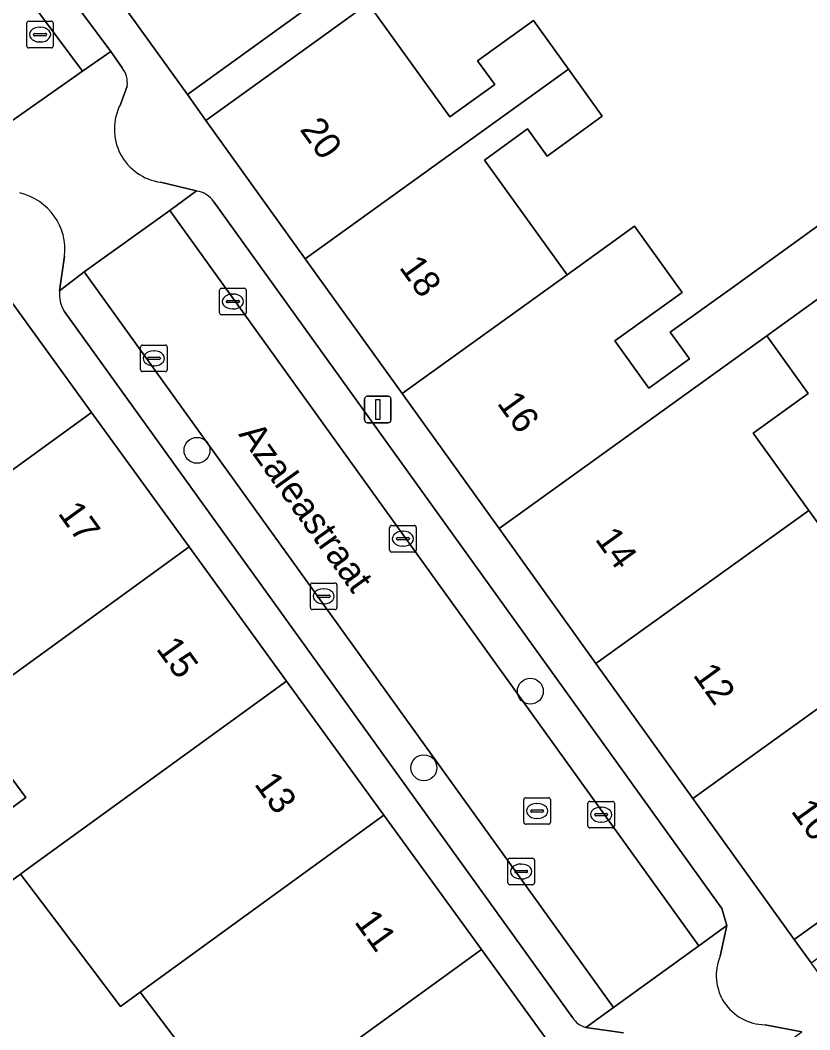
# Model space of a CAD drawing. Extents: x 161881 to 162523, y 381678 to 382381.
# Drawn here: x 162168.42 to 162198.15, y 381942.76 to 381980.78 of the extents above; entities that cross this region are included whole.
import ezdxf

# ---------------------------------------------------------------- set-up
doc = ezdxf.new("R2010")
doc.units = 0
for name, color, linetype in [('IMGEO_Boom', 7, 'Continuous'), ('IMGEO_Erf', 7, 'Continuous'), ('IMGEO_Kolk', 7, 'Continuous'), ('IMGEO_Lichtmast', 7, 'Continuous'), ('IMGEO_Openbare_ruimte_label', 7, 'Continuous'), ('IMGEO_Pand', 7, 'Continuous'), ('IMGEO_Pand_nummerreeks', 7, 'Continuous'), ('IMGEO_Parkeervlak_open', 7, 'Continuous'), ('IMGEO_Rijbaan_lokaal_open', 7, 'Continuous'), ('IMGEO_Rioolput', 7, 'Continuous'), ('IMGEO_Voetpad_open', 7, 'Continuous')]:
    doc.layers.add(name, color=color, linetype=linetype)

msp = doc.modelspace()

# ---------------------------------------------------------------- linework, layer by layer
at = {"layer": 'IMGEO_Boom'}
for centre in [(162175.078, 381964.578), (162187.627, 381955.507), (162183.621, 381952.624)]:
    msp.add_circle(centre, 0.489, dxfattribs=at)
at = {"layer": 'IMGEO_Erf'}
for points in [[(162181.521, 381981.402), (162184.595, 381977.135), (162186.287, 381978.354), (162185.642, 381979.251), (162187.741, 381980.763), (162189.059, 381978.933), (162190.337, 381977.159), (162188.256, 381975.66), (162187.522, 381976.679), (162185.899, 381975.51), (162189.013, 381971.188), (162191.552, 381973.017), (162193.346, 381970.527), (162190.807, 381968.698), (162192.09, 381966.917), (162193.621, 381968.02), (162192.896, 381969.027), (162195.221, 381970.702), (162200.713, 381974.659)], [(162204.344, 381974.538), (162196.525, 381968.892), (162198.089, 381966.721), (162196.011, 381965.224), (162198.108, 381962.315), (162199.336, 381960.612)], [(162175.389, 381940.937), (162172.942, 381944.178), (162172.196, 381943.637), (162169.811, 381946.798), (162168.435, 381948.622), (162167.308, 381947.805), (162167.043, 381947.612), (162165.741, 381949.371), (162167.366, 381950.575), (162168.628, 381951.51), (162166.234, 381954.743), (162164.203, 381953.269), (162164.056, 381953.468), (162163.85, 381953.747), (162161.313, 381957.173), (162162.248, 381957.851), (162161.421, 381958.968), (162160.092, 381960.763), (162162.184, 381962.312), (162162.831, 381961.439), (162164.467, 381962.65), (162161.41, 381966.864), (162140.416, 381951.63)]]:
    msp.add_lwpolyline(points, dxfattribs=at)
at = {"layer": 'IMGEO_Kolk'}
for p, q in [((162168.667, 381979.809), (162168.667, 381980.661)), ((162168.742, 381980.735), (162169.594, 381980.735)), ((162169.155, 381980.515), (162169.18, 381980.515)), ((162169.668, 381980.661), (162169.668, 381979.809)), ((162168.926, 381980.229), (162168.926, 381980.241)), ((162169.364, 381980.192), (162168.966, 381980.192)), ((162168.969, 381980.278), (162169.367, 381980.278)), ((162169.41, 381980.241), (162169.41, 381980.229)), ((162169.594, 381979.735), (162168.742, 381979.735)), ((162169.178, 381979.955), (162169.153, 381979.955)), ((162175.93, 381969.757), (162175.93, 381970.609)), ((162176.005, 381970.683), (162176.857, 381970.683)), ((162176.931, 381970.609), (162176.931, 381969.757)), ((162176.232, 381970.226), (162176.63, 381970.226)), ((162176.418, 381970.463), (162176.443, 381970.463)), ((162176.189, 381970.177), (162176.189, 381970.189)), ((162176.627, 381970.14), (162176.229, 381970.14)), ((162176.441, 381969.903), (162176.416, 381969.903)), ((162176.673, 381970.189), (162176.673, 381970.177)), ((162176.857, 381969.683), (162176.005, 381969.683)), ((162172.955, 381967.616), (162172.955, 381968.468)), ((162173.03, 381968.542), (162173.882, 381968.542)), ((162173.443, 381968.322), (162173.468, 381968.322)), ((162173.956, 381968.468), (162173.956, 381967.616)), ((162173.214, 381968.036), (162173.214, 381968.048)), ((162173.652, 381967.999), (162173.254, 381967.999)), ((162173.257, 381968.085), (162173.655, 381968.085)), ((162173.698, 381968.048), (162173.698, 381968.036)), ((162173.466, 381967.762), (162173.441, 381967.762)), ((162173.882, 381967.542), (162173.03, 381967.542)), ((162182.331, 381960.823), (162182.331, 381961.675)), ((162182.406, 381961.749), (162183.258, 381961.749)), ((162182.819, 381961.529), (162182.844, 381961.529)), ((162183.332, 381961.675), (162183.332, 381960.823)), ((162182.59, 381961.243), (162182.59, 381961.255)), ((162183.028, 381961.206), (162182.63, 381961.206)), ((162182.633, 381961.292), (162183.031, 381961.292)), ((162183.074, 381961.255), (162183.074, 381961.243)), ((162183.258, 381960.749), (162182.406, 381960.749)), ((162182.842, 381960.969), (162182.817, 381960.969)), ((162179.421, 381959.581), (162180.273, 381959.581)), ((162179.346, 381958.655), (162179.346, 381959.507)), ((162179.834, 381959.361), (162179.859, 381959.361)), ((162180.347, 381959.507), (162180.347, 381958.655)), ((162179.605, 381959.075), (162179.605, 381959.087)), ((162180.043, 381959.038), (162179.645, 381959.038)), ((162179.648, 381959.124), (162180.046, 381959.124)), ((162180.089, 381959.087), (162180.089, 381959.075)), ((162180.273, 381958.581), (162179.421, 381958.581)), ((162179.857, 381958.801), (162179.832, 381958.801)), ((162189.792, 381950.433), (162189.792, 381951.285)), ((162189.867, 381951.359), (162190.719, 381951.359)), ((162190.793, 381951.285), (162190.793, 381950.433)), ((162190.051, 381950.853), (162190.051, 381950.865)), ((162190.094, 381950.902), (162190.492, 381950.902)), ((162190.28, 381951.139), (162190.305, 381951.139)), ((162190.535, 381950.865), (162190.535, 381950.853)), ((162190.489, 381950.816), (162190.091, 381950.816)), ((162190.303, 381950.579), (162190.278, 381950.579)), ((162190.719, 381950.359), (162189.867, 381950.359)), ((162186.783, 381948.291), (162186.783, 381949.143)), ((162186.858, 381949.217), (162187.71, 381949.217)), ((162187.271, 381948.997), (162187.296, 381948.997)), ((162187.784, 381949.143), (162187.784, 381948.291)), ((162187.042, 381948.711), (162187.042, 381948.723)), ((162187.48, 381948.674), (162187.082, 381948.674)), ((162187.085, 381948.76), (162187.483, 381948.76)), ((162187.526, 381948.723), (162187.526, 381948.711)), ((162187.71, 381948.217), (162186.858, 381948.217)), ((162187.294, 381948.437), (162187.269, 381948.437))]:
    msp.add_line(p, q, dxfattribs=at)
for points in [[(162168.667, 381979.809), (162168.667, 381980.661)], [(162168.742, 381980.735), (162169.594, 381980.735)], [(162169.668, 381980.661), (162169.668, 381979.809)], [(162169.594, 381979.735), (162168.742, 381979.735)], [(162175.93, 381969.757), (162175.93, 381970.609)], [(162176.005, 381970.683), (162176.857, 381970.683)], [(162176.931, 381970.609), (162176.931, 381969.757)], [(162176.857, 381969.683), (162176.005, 381969.683)], [(162172.955, 381967.616), (162172.955, 381968.468)], [(162173.03, 381968.542), (162173.882, 381968.542)], [(162173.956, 381968.468), (162173.956, 381967.616)], [(162173.882, 381967.542), (162173.03, 381967.542)], [(162182.331, 381960.823), (162182.331, 381961.675)], [(162182.406, 381961.749), (162183.258, 381961.749)], [(162183.332, 381961.675), (162183.332, 381960.823)], [(162183.258, 381960.749), (162182.406, 381960.749)], [(162179.421, 381959.581), (162180.273, 381959.581)], [(162179.346, 381958.655), (162179.346, 381959.507)], [(162180.347, 381959.507), (162180.347, 381958.655)], [(162180.273, 381958.581), (162179.421, 381958.581)], [(162189.792, 381950.433), (162189.792, 381951.285)], [(162189.867, 381951.359), (162190.719, 381951.359)], [(162190.793, 381951.285), (162190.793, 381950.433)], [(162190.719, 381950.359), (162189.867, 381950.359)], [(162186.783, 381948.291), (162186.783, 381949.143)], [(162186.858, 381949.217), (162187.71, 381949.217)], [(162187.784, 381949.143), (162187.784, 381948.291)], [(162187.71, 381948.217), (162186.858, 381948.217)]]:
    msp.add_lwpolyline(points, dxfattribs=at)
for centre, radius, start, end in [((162168.744, 381980.659), 0.0765, 91.552, 178.448), ((162168.744, 381980.659), 0.0765, 91.552, 178.448), ((162169.592, 381980.659), 0.0765, 1.552, 88.448), ((162169.592, 381980.659), 0.0765, 1.552, 88.448), ((162168.966, 381980.238), 0.0403, 85.8775, 175.7526), ((162168.963, 381980.228), 0.0366, 178.938, 274.7102), ((162169.367, 381980.235), 0.043, 264.8664, 352.4533), ((162169.371, 381980.24), 0.0386, 1.7309, 96.639), ((162168.744, 381979.811), 0.0765, 181.552, 268.448), ((162168.744, 381979.811), 0.0765, 181.552, 268.448), ((162169.592, 381979.811), 0.0765, 271.552, 358.448), ((162169.592, 381979.811), 0.0765, 271.552, 358.448), ((162176.007, 381970.607), 0.0765, 91.552, 178.448), ((162176.007, 381970.607), 0.0765, 91.552, 178.448), ((162176.855, 381970.607), 0.0765, 1.552, 88.448), ((162176.855, 381970.607), 0.0765, 1.552, 88.448), ((162176.229, 381970.186), 0.0403, 85.8775, 175.7526), ((162176.634, 381970.188), 0.0386, 1.7309, 96.639), ((162176.226, 381970.176), 0.0366, 178.938, 274.7102), ((162176.63, 381970.183), 0.043, 264.8664, 352.4533), ((162176.007, 381969.759), 0.0765, 181.552, 268.448), ((162176.007, 381969.759), 0.0765, 181.552, 268.448), ((162176.855, 381969.759), 0.0765, 271.552, 358.448), ((162176.855, 381969.759), 0.0765, 271.552, 358.448), ((162173.032, 381968.466), 0.0765, 91.552, 178.448), ((162173.032, 381968.466), 0.0765, 91.552, 178.448), ((162173.88, 381968.466), 0.0765, 1.552, 88.448), ((162173.88, 381968.466), 0.0765, 1.552, 88.448), ((162173.254, 381968.045), 0.0403, 85.8775, 175.7526), ((162173.251, 381968.035), 0.0366, 178.938, 274.7102), ((162173.655, 381968.042), 0.043, 264.8664, 352.4533), ((162173.659, 381968.047), 0.0386, 1.7309, 96.639), ((162173.032, 381967.618), 0.0765, 181.552, 268.448), ((162173.032, 381967.618), 0.0765, 181.552, 268.448), ((162173.88, 381967.618), 0.0765, 271.552, 358.448), ((162173.88, 381967.618), 0.0765, 271.552, 358.448), ((162182.408, 381961.673), 0.0765, 91.552, 178.448), ((162182.408, 381961.673), 0.0765, 91.552, 178.448), ((162183.256, 381961.673), 0.0765, 1.552, 88.448), ((162183.256, 381961.673), 0.0765, 1.552, 88.448), ((162182.63, 381961.252), 0.0403, 85.8775, 175.7526), ((162182.627, 381961.242), 0.0366, 178.938, 274.7102), ((162183.031, 381961.249), 0.043, 264.8664, 352.4533), ((162183.035, 381961.254), 0.0386, 1.7309, 96.639), ((162182.408, 381960.825), 0.0765, 181.552, 268.448), ((162182.408, 381960.825), 0.0765, 181.552, 268.448), ((162183.256, 381960.825), 0.0765, 271.552, 358.448), ((162183.256, 381960.825), 0.0765, 271.552, 358.448), ((162179.423, 381959.505), 0.0765, 91.552, 178.448), ((162179.423, 381959.505), 0.0765, 91.552, 178.448), ((162180.271, 381959.505), 0.0765, 1.552, 88.448), ((162180.271, 381959.505), 0.0765, 1.552, 88.448), ((162179.645, 381959.084), 0.0403, 85.8775, 175.7526), ((162179.642, 381959.074), 0.0366, 178.938, 274.7102), ((162180.046, 381959.081), 0.043, 264.8664, 352.4533), ((162180.05, 381959.086), 0.0386, 1.7309, 96.639), ((162179.423, 381958.657), 0.0765, 181.552, 268.448), ((162179.423, 381958.657), 0.0765, 181.552, 268.448), ((162180.271, 381958.657), 0.0765, 271.552, 358.448), ((162180.271, 381958.657), 0.0765, 271.552, 358.448), ((162189.869, 381951.283), 0.0765, 91.552, 178.448), ((162189.869, 381951.283), 0.0765, 91.552, 178.448), ((162190.717, 381951.283), 0.0765, 1.552, 88.448), ((162190.717, 381951.283), 0.0765, 1.552, 88.448), ((162190.091, 381950.862), 0.0403, 85.8775, 175.7526), ((162190.088, 381950.852), 0.0366, 178.938, 274.7102), ((162190.492, 381950.859), 0.043, 264.8664, 352.4533), ((162190.496, 381950.864), 0.0386, 1.7309, 96.639), ((162189.869, 381950.435), 0.0765, 181.552, 268.448), ((162189.869, 381950.435), 0.0765, 181.552, 268.448), ((162190.717, 381950.435), 0.0765, 271.552, 358.448), ((162190.717, 381950.435), 0.0765, 271.552, 358.448), ((162186.86, 381949.141), 0.0765, 91.552, 178.448), ((162186.86, 381949.141), 0.0765, 91.552, 178.448), ((162187.708, 381949.141), 0.0765, 1.552, 88.448), ((162187.708, 381949.141), 0.0765, 1.552, 88.448), ((162187.082, 381948.72), 0.0403, 85.8775, 175.7526), ((162187.079, 381948.71), 0.0366, 178.938, 274.7102), ((162187.483, 381948.717), 0.043, 264.8664, 352.4533), ((162187.487, 381948.722), 0.0386, 1.7309, 96.639), ((162186.86, 381948.293), 0.0765, 181.552, 268.448), ((162186.86, 381948.293), 0.0765, 181.552, 268.448), ((162187.708, 381948.293), 0.0765, 271.552, 358.448), ((162187.708, 381948.293), 0.0765, 271.552, 358.448)]:
    msp.add_arc(centre, radius, start, end, dxfattribs=at)
for centre, major_axis, ratio, start_param, end_param in [((162169.154, 381980.235), (-0.387, 0.002), 0.722429, 4.712389, 7.853982), ((162169.179, 381980.235), (-0.39, 0.002), 0.717154, 1.570796, 4.712389), ((162176.417, 381970.183), (-0.387, 0.002), 0.722429, 4.712389, 7.853982), ((162176.442, 381970.183), (-0.39, 0.002), 0.717154, 1.570796, 4.712389), ((162173.442, 381968.042), (-0.387, 0.002), 0.722429, 4.712389, 7.853982), ((162173.467, 381968.042), (-0.39, 0.002), 0.717154, 1.570796, 4.712389), ((162182.818, 381961.249), (-0.387, 0.002), 0.722429, 4.712389, 7.853982), ((162182.843, 381961.249), (-0.39, 0.002), 0.717154, 1.570796, 4.712389), ((162179.833, 381959.081), (-0.387, 0.002), 0.722429, 4.712389, 7.853982), ((162179.858, 381959.081), (-0.39, 0.002), 0.717154, 1.570796, 4.712389), ((162190.279, 381950.859), (-0.387, 0.002), 0.722429, 4.712389, 7.853982), ((162190.304, 381950.859), (-0.39, 0.002), 0.717154, 1.570796, 4.712389), ((162187.27, 381948.717), (-0.387, 0.002), 0.722429, 4.712389, 7.853982), ((162187.295, 381948.717), (-0.39, 0.002), 0.717154, 1.570796, 4.712389)]:
    msp.add_ellipse(centre, major_axis=major_axis, ratio=ratio, start_param=start_param, end_param=end_param, dxfattribs=at)
at = {"layer": 'IMGEO_Lichtmast'}
for p, q in [((162181.387, 381965.712), (162181.387, 381966.512)), ((162181.387, 381966.512), (162181.387, 381965.712)), ((162181.487, 381966.612), (162182.277, 381966.612)), ((162182.277, 381966.612), (162181.487, 381966.612)), ((162182.377, 381966.512), (162182.377, 381965.712)), ((162182.377, 381965.712), (162182.377, 381966.512)), ((162182.277, 381965.612), (162181.487, 381965.612)), ((162181.487, 381965.612), (162182.277, 381965.612))]:
    msp.add_line(p, q, dxfattribs=at)
msp.add_lwpolyline([(162181.807, 381966.487), (162181.957, 381966.487), (162181.957, 381965.737), (162181.807, 381965.737), (162181.807, 381966.487)], dxfattribs=at)
for centre, start, end in [((162181.487, 381966.512), 90, 180), ((162181.487, 381966.512), 90, 180), ((162182.277, 381966.512), 0, 90), ((162182.277, 381966.512), 360, 90), ((162181.487, 381965.712), 180, 270), ((162181.487, 381965.712), 180, 270), ((162182.277, 381965.712), 270, 0), ((162182.277, 381965.712), 270, 0)]:
    msp.add_arc(centre, 0.1, start, end, dxfattribs=at)
at = {"layer": 'IMGEO_Pand'}
for points in [[(162170.985, 381983.17), (162174.716, 381977.972), (162178.91, 381980.999), (162180.808, 381982.369), (162177.724, 381986.645), (162179.455, 381987.894), (162180.106, 381986.991), (162180.436, 381986.533), (162183.968, 381989.079), (162182.33, 381991.35)], [(162179.151, 381971.795), (162189.059, 381978.933), (162187.741, 381980.763), (162185.642, 381979.251), (162186.287, 381978.354), (162184.595, 381977.135), (162181.521, 381981.402), (162179.573, 381979.999), (162175.413, 381977.002)], [(162179.151, 381971.795), (162182.8, 381966.712), (162189.013, 381971.188), (162185.899, 381975.51), (162187.522, 381976.679), (162188.256, 381975.66), (162190.337, 381977.159), (162189.059, 381978.933)], [(162190.807, 381968.698), (162193.346, 381970.527), (162191.552, 381973.017), (162189.013, 381971.188), (162182.8, 381966.712), (162186.45, 381961.629), (162196.525, 381968.892), (162204.344, 381974.538), (162203.223, 381976.093), (162200.891, 381974.412), (162200.713, 381974.659), (162195.221, 381970.702), (162192.896, 381969.027), (162193.621, 381968.02), (162192.09, 381966.917)], [(162161.421, 381958.968), (162171.112, 381966), (162167.356, 381971.177), (162163.309, 381968.242), (162161.41, 381966.864), (162164.467, 381962.65), (162162.831, 381961.439), (162162.184, 381962.312), (162160.092, 381960.763)], [(162196.011, 381965.224), (162198.089, 381966.721), (162196.525, 381968.892), (162186.45, 381961.629), (162190.099, 381956.545), (162198.108, 381962.315)], [(162174.78, 381960.944), (162171.112, 381966), (162161.421, 381958.968), (162162.248, 381957.851), (162161.313, 381957.173), (162163.85, 381953.747), (162164.056, 381953.468), (162164.203, 381953.269), (162166.234, 381954.743)], [(162203.804, 381958.705), (162202.529, 381960.475), (162200.492, 381959.008), (162199.591, 381960.257), (162199.336, 381960.612), (162198.108, 381962.315), (162190.099, 381956.545), (162193.749, 381951.462)], [(162178.448, 381955.888), (162174.78, 381960.944), (162166.234, 381954.743), (162168.628, 381951.51), (162167.366, 381950.575), (162165.741, 381949.371), (162167.043, 381947.612), (162167.308, 381947.805), (162168.435, 381948.622), (162168.68, 381948.8)], [(162201.409, 381954.149), (162203.12, 381955.382), (162205.146, 381956.842), (162203.804, 381958.705), (162193.749, 381951.462), (162197.561, 381946.152), (162203.894, 381950.699), (162203.814, 381950.811)], [(162182.116, 381950.833), (162178.448, 381955.888), (162168.68, 381948.8), (162168.435, 381948.622), (162169.811, 381946.798), (162172.196, 381943.637), (162172.942, 381944.178)], [(162182.116, 381950.833), (162172.942, 381944.178), (162175.389, 381940.937), (162174.783, 381940.488), (162176.016, 381938.823), (162180.044, 381941.612), (162185.784, 381945.777)], [(162189.54, 381940.599), (162185.784, 381945.777), (162180.044, 381941.612), (162176.016, 381938.823), (162176.166, 381938.62), (162177.393, 381936.963), (162177.512, 381936.802), (162179.617, 381938.361), (162178.961, 381939.247), (162180.577, 381940.444), (162183.594, 381936.286), (162185.493, 381937.664)]]:
    msp.add_lwpolyline(points, close=True, dxfattribs=at)
at = {"layer": 'IMGEO_Parkeervlak_open'}
msp.add_lwpolyline([(162159.734, 381995.833), (162158.69, 381995.058), (162170.763, 381978.853), (162171.83, 381979.598)], close=True, dxfattribs=at)
for points in [[(162175.055, 381974.344), (162174.049, 381973.615), (162193.973, 381945.919), (162195.028, 381946.682), (162194.84, 381947.327), (162175.715, 381973.938)], [(162170.834, 381971.302), (162169.9, 381970.585)], [(162190.764, 381943.599), (162170.834, 381971.302)], [(162170.081, 381969.816), (162189.211, 381943.219)], [(162189.716, 381942.842), (162190.764, 381943.599)]]:
    msp.add_lwpolyline(points, dxfattribs=at)
for centre, radius, start, end in [((162174.936, 381973.411), 0.94, 34.0698, 82.7346), ((162171.143, 381970.472), 1.248, 174.7931, 211.6963), ((162189.935, 381943.662), 0.848, 211.4501, 255.0647)]:
    msp.add_arc(centre, radius, start, end, dxfattribs=at)
at = {"layer": 'IMGEO_Rijbaan_lokaal_open'}
for points in [[(162158.69, 381995.058), (162155.477, 381992.759), (162167.325, 381976.452), (162170.763, 381978.853)], [(162190.764, 381943.599), (162193.973, 381945.919), (162174.049, 381973.615), (162170.834, 381971.302)]]:
    msp.add_lwpolyline(points, close=True, dxfattribs=at)
for points in [[(162171.83, 381979.598), (162170.763, 381978.853)], [(162172.257, 381978.986), (162171.83, 381979.598)], [(162170.763, 381978.853), (162167.325, 381976.452)], [(162172.195, 381977.605), (162172.446, 381978.298)], [(162175.055, 381974.344), (162173.707, 381974.674)], [(162174.049, 381973.615), (162175.055, 381974.344)], [(162170.834, 381971.302), (162174.049, 381973.615)], [(162170.09, 381971.885), (162169.9, 381970.585)], [(162169.9, 381970.585), (162170.834, 381971.302)], [(162194.772, 381945.533), (162195.028, 381946.682), (162193.973, 381945.919), (162190.764, 381943.599), (162189.716, 381942.842), (162191.13, 381942.643)], [(162192.827, 381940.274), (162192.603, 381938.942), (162193.648, 381939.662), (162196.865, 381941.979), (162197.845, 381942.684), (162196.463, 381942.947)]]:
    msp.add_lwpolyline(points, dxfattribs=at)
for centre, radius, start, end in [((162171.583, 381978.431), 0.873, 351.2551, 39.4665), ((162173.984, 381976.673), 2.018, 152.4796, 262.0956), ((162167.915, 381972.136), 2.189, 353.4203, 76.9885), ((162196.485, 381944.807), 1.86, 157.0387, 269.3231)]:
    msp.add_arc(centre, radius, start, end, dxfattribs=at)
at = {"layer": 'IMGEO_Rioolput'}
for p, q in [((162187.381, 381950.571), (162187.381, 381951.423)), ((162187.456, 381951.497), (162188.308, 381951.497)), ((162187.869, 381951.277), (162187.894, 381951.277)), ((162188.382, 381951.423), (162188.382, 381950.571)), ((162187.64, 381950.991), (162187.64, 381951.003)), ((162188.078, 381950.954), (162187.68, 381950.954)), ((162187.683, 381951.04), (162188.081, 381951.04)), ((162188.124, 381951.003), (162188.124, 381950.991)), ((162188.308, 381950.497), (162187.456, 381950.497)), ((162187.892, 381950.717), (162187.867, 381950.717))]:
    msp.add_line(p, q, dxfattribs=at)
for points in [[(162187.381, 381950.571), (162187.381, 381951.423)], [(162187.456, 381951.497), (162188.308, 381951.497)], [(162188.382, 381951.423), (162188.382, 381950.571)], [(162188.308, 381950.497), (162187.456, 381950.497)]]:
    msp.add_lwpolyline(points, dxfattribs=at)
for centre, radius, start, end in [((162187.458, 381951.421), 0.0765, 91.552, 178.448), ((162187.458, 381951.421), 0.0765, 91.552, 178.448), ((162188.306, 381951.421), 0.0765, 1.552, 88.448), ((162188.306, 381951.421), 0.0765, 1.552, 88.448), ((162187.68, 381951), 0.0403, 85.8775, 175.7526), ((162187.677, 381950.99), 0.0366, 178.938, 274.7102), ((162188.081, 381950.997), 0.043, 264.8664, 352.4533), ((162188.085, 381951.002), 0.0386, 1.7309, 96.639), ((162187.458, 381950.573), 0.0765, 181.552, 268.448), ((162187.458, 381950.573), 0.0765, 181.552, 268.448), ((162188.306, 381950.573), 0.0765, 271.552, 358.448), ((162188.306, 381950.573), 0.0765, 271.552, 358.448)]:
    msp.add_arc(centre, radius, start, end, dxfattribs=at)
for centre, major_axis, ratio, start_param, end_param in [((162187.868, 381950.997), (-0.387, 0.002), 0.722429, 4.712389, 7.853982), ((162187.893, 381950.997), (-0.39, 0.002), 0.717154, 1.570796, 4.712389)]:
    msp.add_ellipse(centre, major_axis=major_axis, ratio=ratio, start_param=start_param, end_param=end_param, dxfattribs=at)
at = {"layer": 'IMGEO_Voetpad_open'}
for points in [[(162159.734, 381995.833), (162171.83, 381979.598), (162172.257, 381978.986)], [(162194.462, 381990.444), (162203.852, 381977.701), (162205.677, 381975.269), (162205.703, 381975.289), (162207.155, 381973.392), (162207.112, 381973.359), (162210.448, 381968.914), (162213.101, 381965.446), (162213.047, 381965.404), (162216.785, 381960.255), (162203.894, 381950.699), (162197.561, 381946.152), (162198.203, 381945.276), (162206.259, 381951.071), (162217.446, 381959.364), (162228.855, 381943.973)], [(162225.13, 381907.844), (162220.871, 381913.764), (162215.596, 381921.098), (162213.628, 381923.833), (162212.953, 381924.771), (162209.198, 381929.992), (162205.532, 381935.088), (162201.866, 381940.184), (162198.203, 381945.276), (162197.561, 381946.152), (162193.749, 381951.462), (162190.099, 381956.545), (162186.45, 381961.629), (162182.8, 381966.712), (162179.151, 381971.795), (162175.413, 381977.002), (162174.716, 381977.972), (162170.985, 381983.17)], [(162159.209, 381982.377), (162162.869, 381977.333), (162166.617, 381972.166), (162167.356, 381971.177), (162171.112, 381966), (162174.78, 381960.944), (162178.448, 381955.888), (162182.116, 381950.833), (162185.784, 381945.777), (162189.54, 381940.599)], [(162178.91, 381980.999), (162174.716, 381977.972), (162175.413, 381977.002), (162179.573, 381979.999), (162181.521, 381981.402)], [(162172.446, 381978.298), (162172.195, 381977.605)], [(162173.707, 381974.674), (162175.055, 381974.344)], [(162175.715, 381973.938), (162194.84, 381947.327), (162195.028, 381946.682), (162194.772, 381945.533)], [(162169.9, 381970.585), (162170.09, 381971.885)], [(162189.211, 381943.219), (162170.081, 381969.816)], [(162191.13, 381942.643), (162189.716, 381942.842)], [(162196.463, 381942.947), (162197.845, 381942.684)]]:
    msp.add_lwpolyline(points, dxfattribs=at)
for centre, radius, start, end in [((162171.583, 381978.431), 0.873, 351.2551, 39.4665), ((162173.984, 381976.673), 2.018, 152.4796, 262.0956), ((162167.915, 381972.136), 2.189, 353.4203, 76.9885), ((162174.936, 381973.411), 0.94, 34.0698, 82.7346), ((162171.143, 381970.472), 1.248, 174.7931, 211.6963), ((162196.485, 381944.807), 1.86, 157.0387, 269.3231), ((162189.935, 381943.662), 0.848, 211.4501, 255.0647)]:
    msp.add_arc(centre, radius, start, end, dxfattribs=at)

# ---------------------------------------------------------------- texts
at = {"layer": 'IMGEO_Openbare_ruimte_label'}
msp.add_text('Azaleastraat', height=1, rotation=305.7241, dxfattribs=at).set_placement((162176.617, 381965.178))
at = {"layer": 'IMGEO_Pand_nummerreeks'}
for s, rotation, p in [('20', 305.7691, (162178.922, 381976.658)), ('18', 305.7691, (162182.663, 381971.465)), ('16', 305.7695, (162186.349, 381966.349)), ('17', 305.9586, (162169.815, 381962.202)), ('14', 305.7695, (162190.036, 381961.231)), ('15', 305.9586, (162173.512, 381957.105)), ('12', 305.7695, (162193.722, 381956.114)), ('13', 305.9586, (162177.209, 381952.009)), ('10', 305.7695, (162197.413, 381950.99)), ('11', 305.9605, (162180.974, 381946.82))]:
    msp.add_text(s, height=1, rotation=rotation, dxfattribs=at).set_placement(p)

doc.saveas('drawing.dxf')
